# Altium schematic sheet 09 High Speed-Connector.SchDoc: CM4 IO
size 420 x 297 mm; Page Create Date: March  8, 1995; Page Number: 9; Page Size: A3; Comment: radxa_1010; Page Count: 19; RevCode: V1.10; Doc: 09 High Speed-Connector; DsnPath: D:\WMS\黄工\[RC126]CM4_IO_V1.10\[RC126]_V1.10\CM4 IO_V1.10.DSN; SchematicName: CM4 IO V1.10; PageName: 09 High Speed-Connector; PageSize: A3; TopSchematic: True
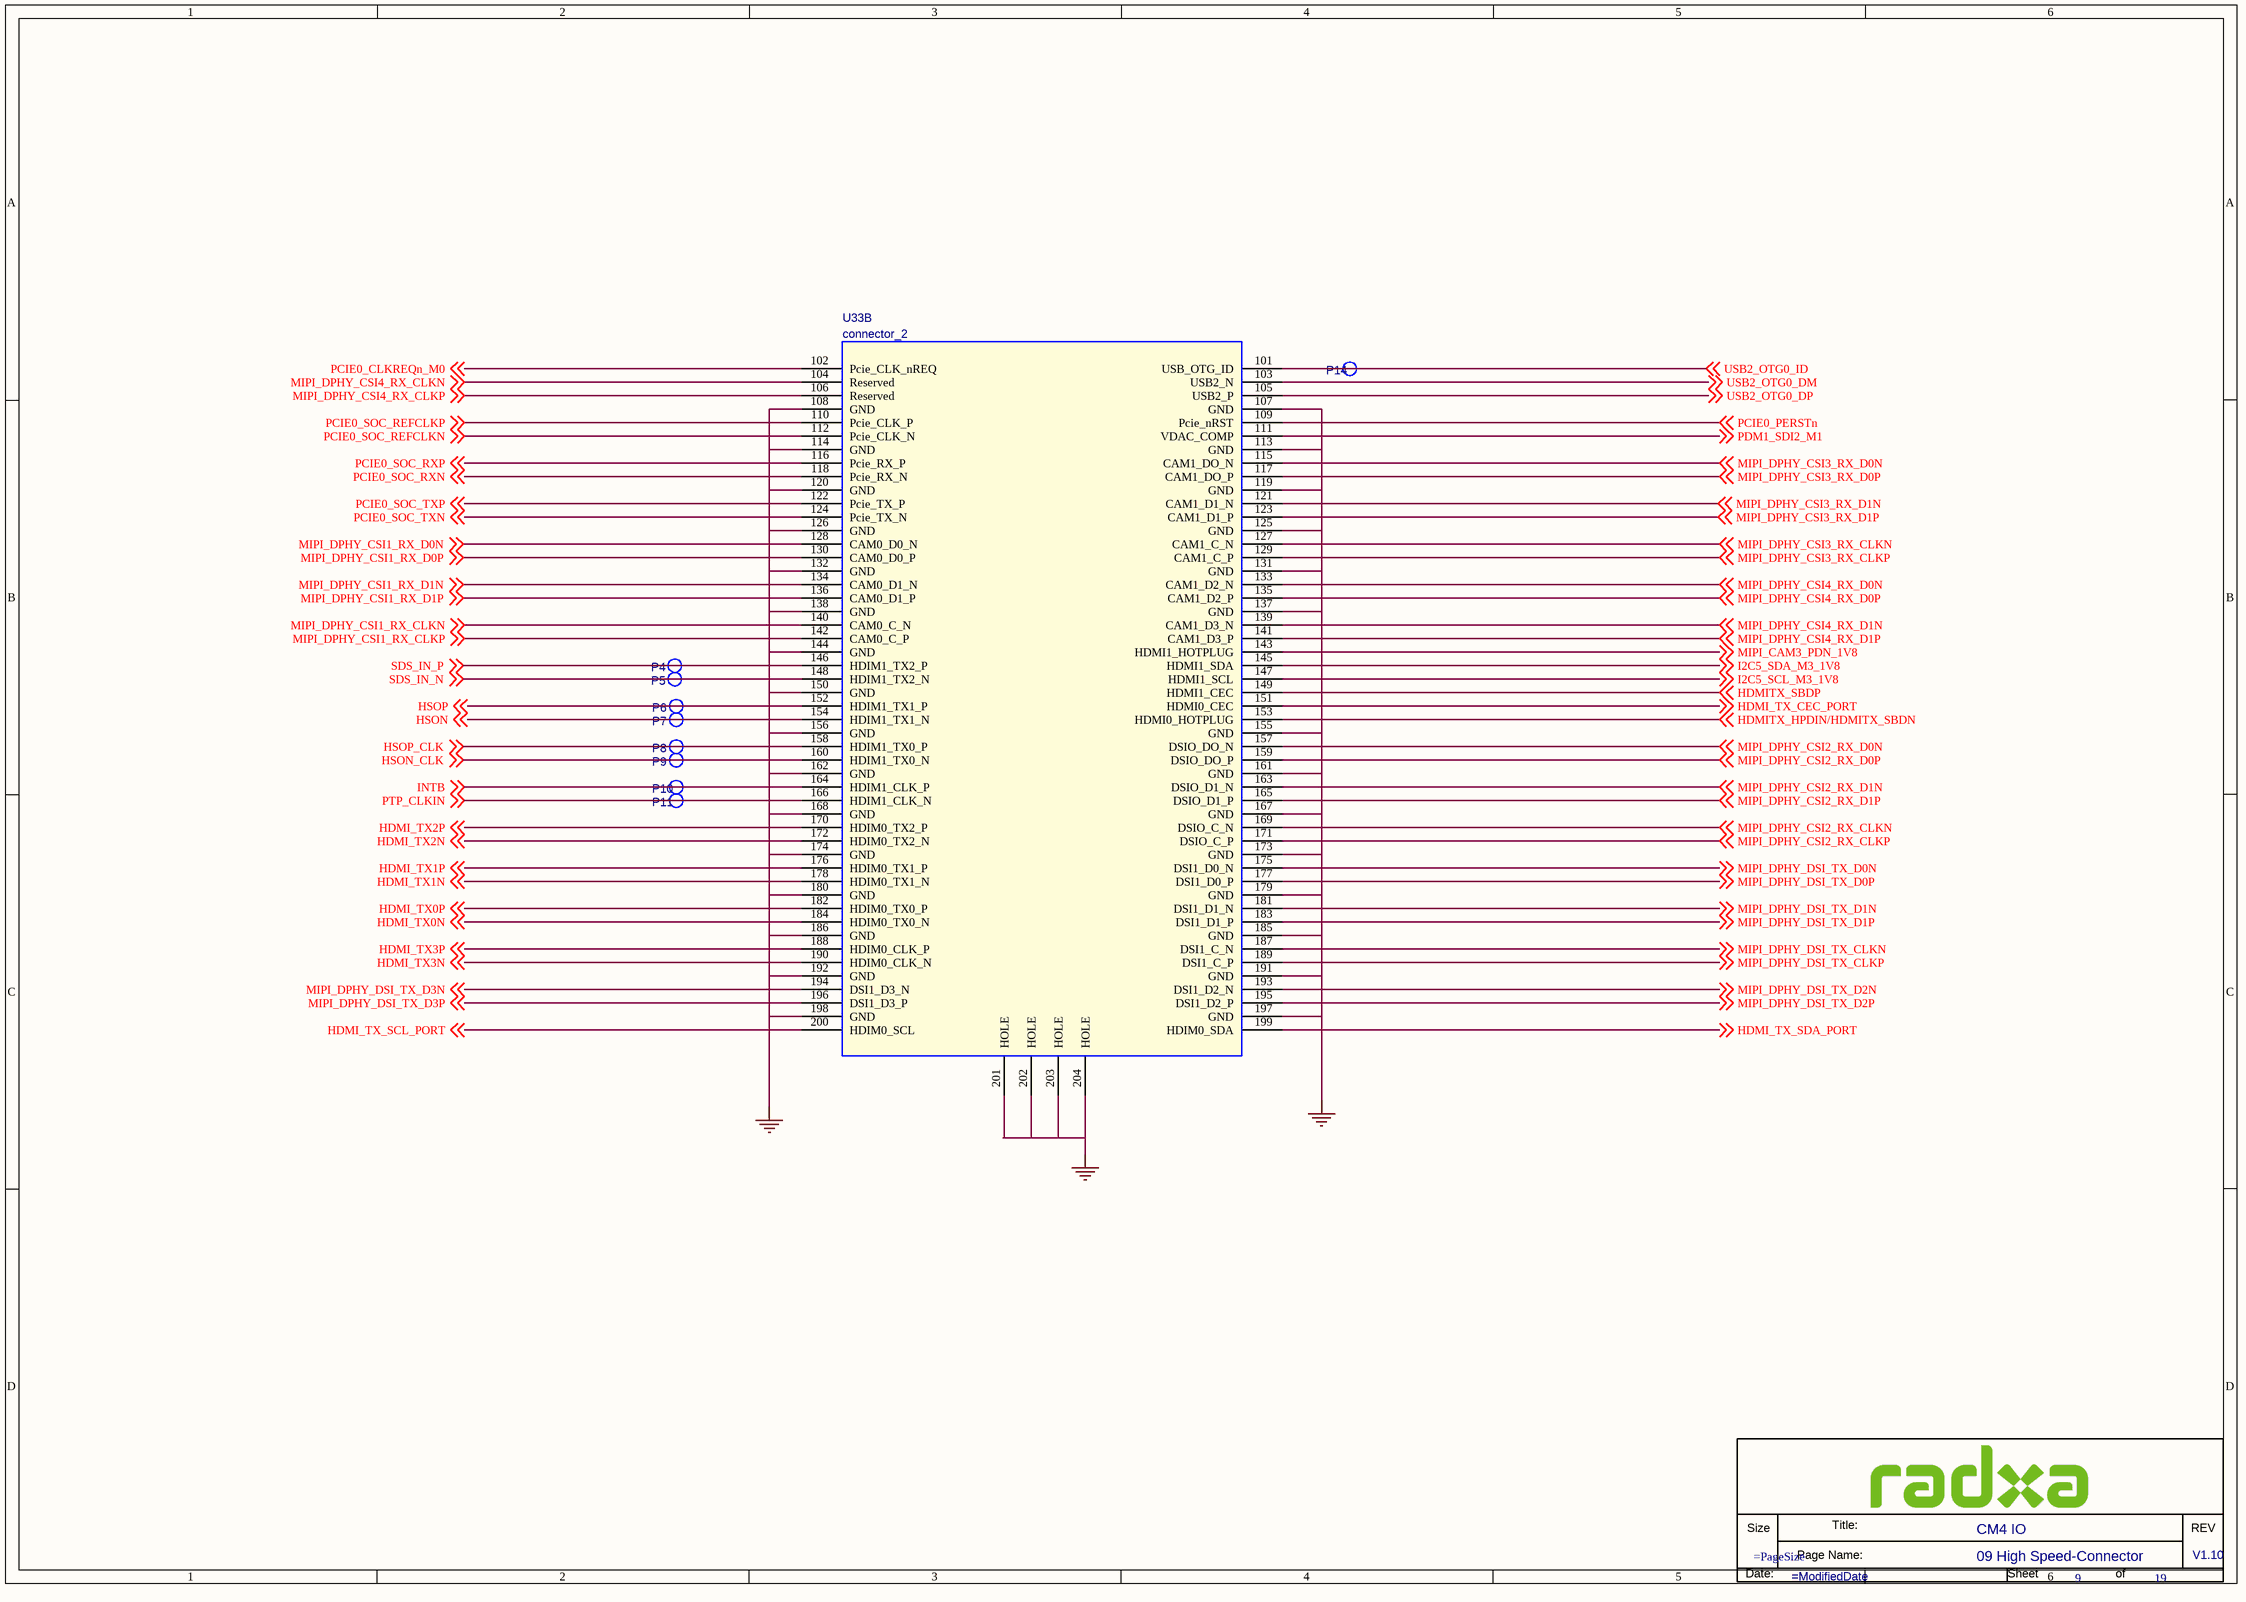
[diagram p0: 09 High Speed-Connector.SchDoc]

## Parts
*  Doc: 09 High Speed-Connector  RevCode: V1.10  Title: CM4 IO  Page Number: 9  Page Count: 19  (hidden comment: radxa_1010)  (graphical)
P4  TEST  [TEST]  (value not drawn)
P5  TEST  [TEST]  (value not drawn)
P6  TEST  [TEST]  (value not drawn)
P7  TEST  [TEST]  (value not drawn)
P8  TEST  [TEST]  (value not drawn)
P9  TEST  [TEST]  (value not drawn)
P10  TEST  [TEST]  (value not drawn)
P11  TEST  [TEST]  (value not drawn)
P14  TEST  [TEST]  (value not drawn)
U33  connector_2  [BTB_SMD100X2_0D4_STA]  (part B of 2)

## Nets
GND: U33.107(GND) U33.108(GND) U33.113(GND) U33.114(GND) U33.119(GND) U33.120(GND) U33.125(GND) U33.126(GND) U33.131(GND) U33.132(GND) U33.137(GND) U33.138(GND) U33.144(GND) U33.150(GND) U33.155(GND) U33.156(GND) U33.161(GND) U33.162(GND) U33.167(GND) U33.168(GND) U33.173(GND) U33.174(GND) U33.179(GND) U33.180(GND) U33.185(GND) U33.186(GND) U33.191(GND) U33.192(GND) U33.197(GND) U33.198(GND) U33.201(HOLE) U33.202(HOLE) U33.203(HOLE) U33.204(HOLE)
HDMI_TX0N: U33.184(HDIM0_TX0_N) ; off-sheet HDMI_TX0N
HDMI_TX0P: U33.182(HDIM0_TX0_P) ; off-sheet HDMI_TX0P
HDMI_TX1N: U33.178(HDIM0_TX1_N) ; off-sheet HDMI_TX1N
HDMI_TX1P: U33.176(HDIM0_TX1_P) ; off-sheet HDMI_TX1P
HDMI_TX2N: U33.172(HDIM0_TX2_N) ; off-sheet HDMI_TX2N
HDMI_TX2P: U33.170(HDIM0_TX2_P) ; off-sheet HDMI_TX2P
HDMI_TX3N: U33.190(HDIM0_CLK_N) ; off-sheet HDMI_TX3N
HDMI_TX3P: U33.188(HDIM0_CLK_P) ; off-sheet HDMI_TX3P
HDMI_TX_CEC_PORT: U33.151(HDMI0_CEC) ; off-sheet HDMI_TX_CEC_PORT
HDMI_TX_SCL_PORT: U33.200(HDIM0_SCL) ; off-sheet HDMI_TX_SCL_PORT
HDMI_TX_SDA_PORT: U33.199(HDIM0_SDA) ; off-sheet HDMI_TX_SDA_PORT
HDMITX_HPDIN/HDMITX_SBDN: U33.153(HDMI0_HOTPLUG) ; off-sheet HDMITX_HPDIN/HDMITX_SBDN
HDMITX_SBDP: U33.149(HDMI1_CEC) ; off-sheet HDMITX_SBDP
HSON: P7.1 U33.154(HDIM1_TX1_N) ; off-sheet HSON
HSON_CLK: P9.1 U33.160(HDIM1_TX0_N) ; off-sheet HSON_CLK
HSOP: P6.1 U33.152(HDIM1_TX1_P) ; off-sheet HSOP
HSOP_CLK: P8.1 U33.158(HDIM1_TX0_P) ; off-sheet HSOP_CLK
I2C5_SCL_M3_1V8: U33.147(HDMI1_SCL) ; off-sheet I2C5_SCL_M3_1V8
I2C5_SDA_M3_1V8: U33.145(HDMI1_SDA) ; off-sheet I2C5_SDA_M3_1V8
INTB: P10.1 U33.164(HDIM1_CLK_P) ; off-sheet INTB
MIPI_CAM3_PDN_1V8: U33.143(HDMI1_HOTPLUG) ; off-sheet MIPI_CAM3_PDN_1V8
MIPI_DPHY_CSI1_RX_CLKN: U33.140(CAM0_C_N) ; off-sheet MIPI_DPHY_CSI1_RX_CLKN
MIPI_DPHY_CSI1_RX_CLKP: U33.142(CAM0_C_P) ; off-sheet MIPI_DPHY_CSI1_RX_CLKP
MIPI_DPHY_CSI1_RX_D0N: U33.128(CAM0_D0_N) ; off-sheet MIPI_DPHY_CSI1_RX_D0N
MIPI_DPHY_CSI1_RX_D0P: U33.130(CAM0_D0_P) ; off-sheet MIPI_DPHY_CSI1_RX_D0P
MIPI_DPHY_CSI1_RX_D1N: U33.134(CAM0_D1_N) ; off-sheet MIPI_DPHY_CSI1_RX_D1N
MIPI_DPHY_CSI1_RX_D1P: U33.136(CAM0_D1_P) ; off-sheet MIPI_DPHY_CSI1_RX_D1P
MIPI_DPHY_CSI2_RX_CLKN: U33.169(DSIO_C_N) ; off-sheet MIPI_DPHY_CSI2_RX_CLKN
MIPI_DPHY_CSI2_RX_CLKP: U33.171(DSIO_C_P) ; off-sheet MIPI_DPHY_CSI2_RX_CLKP
MIPI_DPHY_CSI2_RX_D0N: U33.157(DSIO_DO_N) ; off-sheet MIPI_DPHY_CSI2_RX_D0N
MIPI_DPHY_CSI2_RX_D0P: U33.159(DSIO_DO_P) ; off-sheet MIPI_DPHY_CSI2_RX_D0P
MIPI_DPHY_CSI2_RX_D1N: U33.163(DSIO_D1_N) ; off-sheet MIPI_DPHY_CSI2_RX_D1N
MIPI_DPHY_CSI2_RX_D1P: U33.165(DSIO_D1_P) ; off-sheet MIPI_DPHY_CSI2_RX_D1P
MIPI_DPHY_CSI3_RX_CLKN: U33.127(CAM1_C_N) ; off-sheet MIPI_DPHY_CSI3_RX_CLKN
MIPI_DPHY_CSI3_RX_CLKP: U33.129(CAM1_C_P) ; off-sheet MIPI_DPHY_CSI3_RX_CLKP
MIPI_DPHY_CSI3_RX_D0N: U33.115(CAM1_DO_N) ; off-sheet MIPI_DPHY_CSI3_RX_D0N
MIPI_DPHY_CSI3_RX_D0P: U33.117(CAM1_DO_P) ; off-sheet MIPI_DPHY_CSI3_RX_D0P
MIPI_DPHY_CSI3_RX_D1N: U33.121(CAM1_D1_N) ; off-sheet MIPI_DPHY_CSI3_RX_D1N
MIPI_DPHY_CSI3_RX_D1P: U33.123(CAM1_D1_P) ; off-sheet MIPI_DPHY_CSI3_RX_D1P
MIPI_DPHY_CSI4_RX_CLKN: U33.104(Reserved) ; off-sheet MIPI_DPHY_CSI4_RX_CLKN
MIPI_DPHY_CSI4_RX_CLKP: U33.106(Reserved) ; off-sheet MIPI_DPHY_CSI4_RX_CLKP
MIPI_DPHY_CSI4_RX_D0N: U33.133(CAM1_D2_N) ; off-sheet MIPI_DPHY_CSI4_RX_D0N
MIPI_DPHY_CSI4_RX_D0P: U33.135(CAM1_D2_P) ; off-sheet MIPI_DPHY_CSI4_RX_D0P
MIPI_DPHY_CSI4_RX_D1N: U33.139(CAM1_D3_N) ; off-sheet MIPI_DPHY_CSI4_RX_D1N
MIPI_DPHY_CSI4_RX_D1P: U33.141(CAM1_D3_P) ; off-sheet MIPI_DPHY_CSI4_RX_D1P
MIPI_DPHY_DSI_TX_CLKN: U33.187(DSI1_C_N) ; off-sheet MIPI_DPHY_DSI_TX_CLKN
MIPI_DPHY_DSI_TX_CLKP: U33.189(DSI1_C_P) ; off-sheet MIPI_DPHY_DSI_TX_CLKP
MIPI_DPHY_DSI_TX_D0N: U33.175(DSI1_D0_N) ; off-sheet MIPI_DPHY_DSI_TX_D0N
MIPI_DPHY_DSI_TX_D0P: U33.177(DSI1_D0_P) ; off-sheet MIPI_DPHY_DSI_TX_D0P
MIPI_DPHY_DSI_TX_D1N: U33.181(DSI1_D1_N) ; off-sheet MIPI_DPHY_DSI_TX_D1N
MIPI_DPHY_DSI_TX_D1P: U33.183(DSI1_D1_P) ; off-sheet MIPI_DPHY_DSI_TX_D1P
MIPI_DPHY_DSI_TX_D2N: U33.193(DSI1_D2_N) ; off-sheet MIPI_DPHY_DSI_TX_D2N
MIPI_DPHY_DSI_TX_D2P: U33.195(DSI1_D2_P) ; off-sheet MIPI_DPHY_DSI_TX_D2P
MIPI_DPHY_DSI_TX_D3N: U33.194(DSI1_D3_N) ; off-sheet MIPI_DPHY_DSI_TX_D3N
MIPI_DPHY_DSI_TX_D3P: U33.196(DSI1_D3_P) ; off-sheet MIPI_DPHY_DSI_TX_D3P
PCIE0_CLKREQn_M0: U33.102(Pcie_CLK_nREQ) ; off-sheet PCIE0_CLKREQn_M0
PCIE0_PERSTn: U33.109(Pcie_nRST) ; off-sheet PCIE0_PERSTn
PCIE0_SOC_REFCLKN: U33.112(Pcie_CLK_N) ; off-sheet PCIE0_SOC_REFCLKN
PCIE0_SOC_REFCLKP: U33.110(Pcie_CLK_P) ; off-sheet PCIE0_SOC_REFCLKP
PCIE0_SOC_RXN: U33.118(Pcie_RX_N) ; off-sheet PCIE0_SOC_RXN
PCIE0_SOC_RXP: U33.116(Pcie_RX_P) ; off-sheet PCIE0_SOC_RXP
PCIE0_SOC_TXN: U33.124(Pcie_TX_N) ; off-sheet PCIE0_SOC_TXN
PCIE0_SOC_TXP: U33.122(Pcie_TX_P) ; off-sheet PCIE0_SOC_TXP
PDM1_SDI2_M1: U33.111(VDAC_COMP) ; off-sheet PDM1_SDI2_M1
PTP_CLKIN: P11.1 U33.166(HDIM1_CLK_N) ; off-sheet PTP_CLKIN
SDS_IN_N: P5.1 U33.148(HDIM1_TX2_N) ; off-sheet SDS_IN_N
SDS_IN_P: P4.1 U33.146(HDIM1_TX2_P) ; off-sheet SDS_IN_P
USB2_OTG0_DM: U33.103(USB2_N) ; off-sheet USB2_OTG0_DM
USB2_OTG0_DP: U33.105(USB2_P) ; off-sheet USB2_OTG0_DP
USB2_OTG0_ID: P14.1 U33.101(USB_OTG_ID) ; off-sheet USB2_OTG0_ID

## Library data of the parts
P4 = TESTPOINT1: Part Reference: P4; PCB Footprint: TP_0R70
P5 = TESTPOINT1: Part Reference: P5; PCB Footprint: TP_0R70
P6 = TESTPOINT1: Part Reference: P6; PCB Footprint: TP_0R70
P7 = TESTPOINT1: Part Reference: P7; PCB Footprint: TP_0R70
P8 = TESTPOINT1: Part Reference: P8; PCB Footprint: TP_0R70
P9 = TESTPOINT1: Part Reference: P9; PCB Footprint: TP_0R70
P10 = TESTPOINT1: Part Reference: P10; PCB Footprint: TP_0R70
P11 = TESTPOINT1: Part Reference: P11; PCB Footprint: TP_0R70
P14 = TESTPOINT1: Part Reference: P14; PCB Footprint: TP_0R70
U33 = HETER_4: Part Reference: U33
